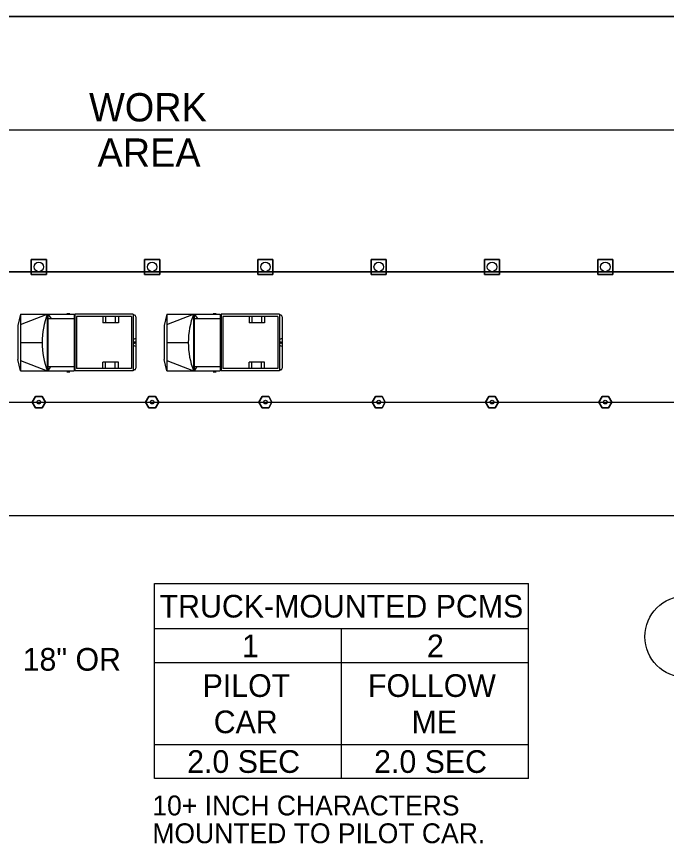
# Model space of a CAD drawing. Extents: x 99998.9 to 100095.7, y 99995 to 100010.7.
# Drawn here: x 100047.071 to 100049.366, y 100004.575 to 100007.492 of the extents above; entities that cross this region are included whole.
import ezdxf

# ---------------------------------------------------------------- set-up
doc = ezdxf.new("R2010")
doc.units = 0
for name, color, linetype in [('RD_ED_ShoulderPavedEdge', 7, 'Continuous'), ('RD_MK_LineEdgeWhite', 7, 'Continuous'), ('RD_MK_LineSkipCenter', 7, 'Continuous'), ('SH_GI_SectionCut', 7, 'Continuous'), ('TR_SN_ConstructionSigns', 7, 'Continuous'), ('TR_WZ_MotoristVehicle', 7, 'Continuous'), ('TR_WZ_PortableChangeMessageSign', 7, 'Continuous'), ('TR_WZ_TrafficCone', 7, 'Continuous'), ('TR_WZ_TubularMarker', 7, 'Continuous'), ('TR_WZ_WorkAreaLabel', 7, 'Continuous'), ('TR_WZ_WorkZoneDetails', 7, 'Continuous')]:
    doc.layers.add(name, color=color, linetype=linetype)

msp = doc.modelspace()

# ---------------------------------------------------------------- linework, layer by layer
at = {"layer": 'RD_ED_ShoulderPavedEdge'}
for p, q in [((100040.1076, 100007.4923), (100055.6424, 100007.4923)), ((100040.1076, 100005.7323), (100055.6424, 100005.7323))]:
    msp.add_line(p, q, dxfattribs=at)
at = {"layer": 'RD_MK_LineEdgeWhite'}
for p, q in [((100040.1076, 100007.0923), (100055.6424, 100007.0923)), ((100040.1076, 100006.1323), (100055.6424, 100006.1323))]:
    msp.add_line(p, q, dxfattribs=at)
at = {"layer": 'RD_MK_LineSkipCenter'}
msp.add_lwpolyline([(100051.15, 100006.5923), (100043.4767, 100006.5923)], dxfattribs=at)
at = {"layer": 'SH_GI_SectionCut'}
msp.add_circle((100049.4338, 100005.3048), 0.144, dxfattribs=at)
at = {"layer": 'TR_WZ_MotoristVehicle'}
for p, q in [((100047.0856, 100006.4423), (100047.0763, 100006.402)), ((100047.0856, 100006.4423), (100047.0856, 100006.2423)), ((100047.0856, 100006.4423), (100047.2745, 100006.4423)), ((100047.0856, 100006.4057), (100047.18, 100006.4423)), ((100047.18, 100006.4423), (100047.18, 100006.2423)), ((100047.1817, 100006.4423), (100047.1817, 100006.2423)), ((100047.1817, 100006.4423), (100047.1938, 100006.4268)), ((100047.2487, 100006.4451), (100047.26, 100006.4451)), ((100047.2745, 100006.4423), (100047.2745, 100006.2423)), ((100047.4829, 100006.4423), (100047.2772, 100006.4423)), ((100047.2772, 100006.4423), (100047.2772, 100006.2423)), ((100047.4829, 100006.4423), (100047.4829, 100006.2423)), ((100047.6018, 100006.4423), (100047.5926, 100006.402)), ((100047.6018, 100006.4423), (100047.6018, 100006.2423)), ((100047.6018, 100006.4423), (100047.7907, 100006.4423)), ((100047.6018, 100006.4057), (100047.6963, 100006.4423)), ((100047.6963, 100006.4423), (100047.6963, 100006.2423)), ((100047.698, 100006.4423), (100047.698, 100006.2423)), ((100047.698, 100006.4423), (100047.71, 100006.4268)), ((100047.765, 100006.4451), (100047.7763, 100006.4451)), ((100047.7907, 100006.4423), (100047.7907, 100006.2423)), ((100047.9992, 100006.4423), (100047.7935, 100006.4423)), ((100047.7935, 100006.4423), (100047.7935, 100006.2423)), ((100047.9992, 100006.4423), (100047.9992, 100006.2423)), ((100047.1817, 100006.4268), (100047.2745, 100006.4268)), ((100047.4771, 100006.4344), (100047.2831, 100006.4344)), ((100047.2831, 100006.4344), (100047.2831, 100006.2503)), ((100047.3758, 100006.4344), (100047.3758, 100006.4113)), ((100047.3857, 100006.4344), (100047.3857, 100006.4113)), ((100047.4197, 100006.4344), (100047.4197, 100006.4113)), ((100047.4307, 100006.4344), (100047.4307, 100006.4113)), ((100047.4771, 100006.4344), (100047.4771, 100006.2503)), ((100047.4881, 100006.439), (100047.4836, 100006.439)), ((100047.4836, 100006.439), (100047.4836, 100006.2456)), ((100047.4926, 100006.4329), (100047.4926, 100006.2517)), ((100047.698, 100006.4268), (100047.7907, 100006.4268)), ((100047.9934, 100006.4344), (100047.7993, 100006.4344)), ((100047.7993, 100006.4344), (100047.7993, 100006.2503)), ((100047.892, 100006.4344), (100047.892, 100006.4113)), ((100047.902, 100006.4344), (100047.902, 100006.4113)), ((100047.936, 100006.4344), (100047.936, 100006.4113)), ((100047.947, 100006.4344), (100047.947, 100006.4113)), ((100047.9934, 100006.4344), (100047.9934, 100006.2503)), ((100048.0044, 100006.439), (100047.9999, 100006.439)), ((100047.9999, 100006.439), (100047.9999, 100006.2456)), ((100048.0088, 100006.4329), (100048.0088, 100006.2517)), ((100047.0763, 100006.402), (100047.0763, 100006.2827)), ((100047.4307, 100006.4113), (100047.3758, 100006.4113)), ((100047.5926, 100006.402), (100047.5926, 100006.2827)), ((100047.947, 100006.4113), (100047.892, 100006.4113)), ((100047.4926, 100006.3564), (100047.4836, 100006.3527)), ((100048.0088, 100006.3564), (100047.9999, 100006.3527)), ((100047.0856, 100006.3423), (100047.1615, 100006.3423)), ((100047.4926, 100006.3282), (100047.4836, 100006.332)), ((100047.4902, 100006.3423), (100047.486, 100006.3423)), ((100047.4881, 100006.3451), (100047.4881, 100006.3395)), ((100047.6018, 100006.3423), (100047.6777, 100006.3423)), ((100048.0088, 100006.3282), (100047.9999, 100006.332)), ((100048.0064, 100006.3423), (100048.0023, 100006.3423)), ((100048.0044, 100006.3451), (100048.0044, 100006.3395)), ((100047.0856, 100006.2423), (100047.0763, 100006.2827)), ((100047.0856, 100006.279), (100047.18, 100006.2423)), ((100047.3758, 100006.2503), (100047.3758, 100006.2733)), ((100047.4307, 100006.2733), (100047.3758, 100006.2733)), ((100047.3857, 100006.2503), (100047.3857, 100006.2733)), ((100047.4197, 100006.2503), (100047.4197, 100006.2733)), ((100047.4307, 100006.2503), (100047.4307, 100006.2733)), ((100047.6018, 100006.2423), (100047.5926, 100006.2827)), ((100047.6018, 100006.279), (100047.6963, 100006.2423)), ((100047.892, 100006.2503), (100047.892, 100006.2733)), ((100047.947, 100006.2733), (100047.892, 100006.2733)), ((100047.902, 100006.2503), (100047.902, 100006.2733)), ((100047.936, 100006.2503), (100047.936, 100006.2733)), ((100047.947, 100006.2503), (100047.947, 100006.2733)), ((100047.0856, 100006.2423), (100047.2745, 100006.2423)), ((100047.1817, 100006.2578), (100047.2745, 100006.2578)), ((100047.1917, 100006.2578), (100047.1817, 100006.2423)), ((100047.2487, 100006.2395), (100047.26, 100006.2395)), ((100047.4829, 100006.2423), (100047.2772, 100006.2423)), ((100047.4771, 100006.2503), (100047.2831, 100006.2503)), ((100047.4881, 100006.2456), (100047.4836, 100006.2456)), ((100047.6018, 100006.2423), (100047.7907, 100006.2423)), ((100047.698, 100006.2578), (100047.7907, 100006.2578)), ((100047.708, 100006.2578), (100047.698, 100006.2423)), ((100047.765, 100006.2395), (100047.7763, 100006.2395)), ((100047.9992, 100006.2423), (100047.7935, 100006.2423)), ((100047.9934, 100006.2503), (100047.7993, 100006.2503)), ((100048.0044, 100006.2456), (100047.9999, 100006.2456))]:
    msp.add_line(p, q, dxfattribs=at)
for centre, major_axis, start_param, end_param in [((100047.315, 100006.3423), (0, -0.2099), 4.215667, 5.208926), ((100047.8313, 100006.3423), (0, -0.2099), 4.215667, 5.208926), ((100047.4881, 100006.4329), (0, 0.0061), 4.712389, 6.283185), ((100048.0044, 100006.4329), (0, 0.0061), 4.712389, 6.283185), ((100047.4881, 100006.2517), (0, -0.0061), 0, 1.570796), ((100048.0044, 100006.2517), (0, -0.0061), 0, 1.570796)]:
    msp.add_ellipse(centre, major_axis=major_axis, ratio=0.73155, start_param=start_param, end_param=end_param, dxfattribs=at)
for centre in [(100047.4881, 100006.3423), (100048.0044, 100006.3423)]:
    msp.add_ellipse(centre, major_axis=(0, 0.00282), ratio=0.73155, dxfattribs=at)
at = {"layer": 'TR_WZ_PortableChangeMessageSign'}
for p, q in [((100047.5582, 100005.4923), (100048.8782, 100005.4923)), ((100047.5582, 100004.8043), (100047.5582, 100005.4923)), ((100048.8782, 100004.8043), (100048.8782, 100005.4923)), ((100048.8782, 100005.3323), (100047.5582, 100005.3323)), ((100048.2182, 100004.8043), (100048.2182, 100005.3323)), ((100048.2182, 100005.2123), (100047.5582, 100005.2123)), ((100048.8782, 100005.2123), (100048.2182, 100005.2123)), ((100047.5582, 100004.9243), (100048.2182, 100004.9243)), ((100048.2182, 100004.9243), (100048.8782, 100004.9243)), ((100048.8782, 100004.8043), (100047.5582, 100004.8043))]:
    msp.add_line(p, q, dxfattribs=at)
at = {"layer": 'TR_WZ_TrafficCone'}
for points in [[(100047.1234, 100006.6357), (100047.1767, 100006.6357), (100047.1767, 100006.5823), (100047.1234, 100006.5823), (100047.1234, 100006.6357)], [(100047.1234, 100006.5823), (100047.1767, 100006.5823), (100047.1767, 100006.6357), (100047.1234, 100006.6357), (100047.1234, 100006.5823)], [(100047.5234, 100006.6357), (100047.5767, 100006.6357), (100047.5767, 100006.5823), (100047.5234, 100006.5823), (100047.5234, 100006.6357)], [(100047.5234, 100006.5823), (100047.5767, 100006.5823), (100047.5767, 100006.6357), (100047.5234, 100006.6357), (100047.5234, 100006.5823)], [(100047.9234, 100006.6357), (100047.9767, 100006.6357), (100047.9767, 100006.5823), (100047.9234, 100006.5823), (100047.9234, 100006.6357)], [(100047.9234, 100006.5823), (100047.9767, 100006.5823), (100047.9767, 100006.6357), (100047.9234, 100006.6357), (100047.9234, 100006.5823)], [(100048.3234, 100006.6357), (100048.3767, 100006.6357), (100048.3767, 100006.5823), (100048.3234, 100006.5823), (100048.3234, 100006.6357)], [(100048.3234, 100006.5823), (100048.3767, 100006.5823), (100048.3767, 100006.6357), (100048.3234, 100006.6357), (100048.3234, 100006.5823)], [(100048.7234, 100006.6357), (100048.7767, 100006.6357), (100048.7767, 100006.5823), (100048.7234, 100006.5823), (100048.7234, 100006.6357)], [(100048.7234, 100006.5823), (100048.7767, 100006.5823), (100048.7767, 100006.6357), (100048.7234, 100006.6357), (100048.7234, 100006.5823)], [(100049.1234, 100006.6357), (100049.1767, 100006.6357), (100049.1767, 100006.5823), (100049.1234, 100006.5823), (100049.1234, 100006.6357)], [(100049.1234, 100006.5823), (100049.1767, 100006.5823), (100049.1767, 100006.6357), (100049.1234, 100006.6357), (100049.1234, 100006.5823)]]:
    msp.add_lwpolyline(points, dxfattribs=at)
for centre in [(100047.15, 100006.609), (100047.55, 100006.609), (100047.95, 100006.609), (100048.35, 100006.609), (100048.75, 100006.609), (100049.15, 100006.609)]:
    msp.add_circle(centre, 0.0167, dxfattribs=at)
at = {"layer": 'TR_WZ_TubularMarker'}
for points in [[(100047.1269, 100006.1323), (100047.1385, 100006.1523), (100047.1616, 100006.1523), (100047.1731, 100006.1323), (100047.1616, 100006.1123), (100047.1385, 100006.1123)], [(100047.5269, 100006.1323), (100047.5385, 100006.1523), (100047.5616, 100006.1523), (100047.5731, 100006.1323), (100047.5616, 100006.1123), (100047.5385, 100006.1123)], [(100047.9269, 100006.1323), (100047.9385, 100006.1523), (100047.9616, 100006.1523), (100047.9731, 100006.1323), (100047.9616, 100006.1123), (100047.9385, 100006.1123)], [(100048.3269, 100006.1323), (100048.3385, 100006.1523), (100048.3616, 100006.1523), (100048.3731, 100006.1323), (100048.3616, 100006.1123), (100048.3385, 100006.1123)], [(100048.7269, 100006.1323), (100048.7385, 100006.1523), (100048.7616, 100006.1523), (100048.7731, 100006.1323), (100048.7616, 100006.1123), (100048.7385, 100006.1123)], [(100049.1269, 100006.1323), (100049.1385, 100006.1523), (100049.1616, 100006.1523), (100049.1731, 100006.1323), (100049.1616, 100006.1123), (100049.1385, 100006.1123)]]:
    msp.add_lwpolyline(points, close=True, dxfattribs=at)
for points in [[(100047.1385, 100006.1123), (100047.1616, 100006.1123), (100047.1731, 100006.1323), (100047.1616, 100006.1523), (100047.1385, 100006.1523), (100047.1269, 100006.1323), (100047.1385, 100006.1123)], [(100047.5385, 100006.1123), (100047.5616, 100006.1123), (100047.5731, 100006.1323), (100047.5616, 100006.1523), (100047.5385, 100006.1523), (100047.5269, 100006.1323), (100047.5385, 100006.1123)], [(100047.9385, 100006.1123), (100047.9616, 100006.1123), (100047.9731, 100006.1323), (100047.9616, 100006.1523), (100047.9385, 100006.1523), (100047.9269, 100006.1323), (100047.9385, 100006.1123)], [(100048.3385, 100006.1123), (100048.3616, 100006.1123), (100048.3731, 100006.1323), (100048.3616, 100006.1523), (100048.3385, 100006.1523), (100048.3269, 100006.1323), (100048.3385, 100006.1123)], [(100048.7385, 100006.1123), (100048.7616, 100006.1123), (100048.7731, 100006.1323), (100048.7616, 100006.1523), (100048.7385, 100006.1523), (100048.7269, 100006.1323), (100048.7385, 100006.1123)], [(100049.1385, 100006.1123), (100049.1616, 100006.1123), (100049.1731, 100006.1323), (100049.1616, 100006.1523), (100049.1385, 100006.1523), (100049.1269, 100006.1323), (100049.1385, 100006.1123)]]:
    msp.add_lwpolyline(points, dxfattribs=at)
for centre in [(100047.15, 100006.1323), (100047.55, 100006.1323), (100047.95, 100006.1323), (100048.35, 100006.1323), (100048.75, 100006.1323), (100049.15, 100006.1323)]:
    msp.add_circle(centre, 0.00667, dxfattribs=at)
at = {"layer": 'TR_WZ_WorkZoneDetails'}
msp.add_lwpolyline([(100045.15, 100007.4923), (100045.15, 100006.5923), (100049.9338, 100006.5923), (100049.9338, 100007.4923)], close=True, dxfattribs=at)

# ---------------------------------------------------------------- texts
at = {"layer": 'TR_SN_ConstructionSigns'}
msp.add_text('18" OR', height=0.08, rotation=360, dxfattribs=at).set_placement((100047.0928, 100005.1848))
at = {"layer": 'TR_WZ_PortableChangeMessageSign'}
for s, height, p in [('TRUCK-MOUNTED PCMS', 0.08, (100047.5765, 100005.3723)), ('1', 0.08, (100047.8671, 100005.2323)), ('2', 0.08, (100048.5203, 100005.2323)), ('PILOT', 0.08, (100047.7283, 100005.0923)), ('FOLLOW', 0.08, (100048.3121, 100005.0923)), ('CAR', 0.08, (100047.7675, 100004.9643)), ('ME', 0.08, (100048.466, 100004.9643)), ('2.0 SEC', 0.08, (100047.6738, 100004.8243)), ('2.0 SEC', 0.08, (100048.3338, 100004.8243)), ('10+ INCH CHARACTERS', 0.07, (100047.5507, 100004.6743)), ('MOUNTED TO PILOT CAR.', 0.07, (100047.5507, 100004.5763))]:
    msp.add_text(s, height=height, rotation=360, dxfattribs=at).set_placement(p)
at = {"layer": 'TR_WZ_WorkAreaLabel'}
for s, p in [('WORK', (100047.3273, 100007.1223)), ('AREA', (100047.357, 100006.9623))]:
    msp.add_text(s, height=0.1, dxfattribs=at).set_placement(p)

doc.saveas('drawing.dxf')
